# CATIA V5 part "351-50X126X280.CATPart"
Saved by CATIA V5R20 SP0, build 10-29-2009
Part number: 351-50X126X280
Definition: NONE
Nomenclature: 351-50X126X280
Source: Unknown
Description: 351-50X126X280
Bounding box of the stored display mesh (mm): x -10 to 270, y -32.5 to 32.5, z -32.5 to 32.5
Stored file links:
  C:\Users\Utente\Desktop\IO LAVORO\3D X SITO CF\X SITO\PLASTICA\351\351-50X126X280.CATPart
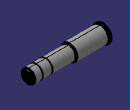
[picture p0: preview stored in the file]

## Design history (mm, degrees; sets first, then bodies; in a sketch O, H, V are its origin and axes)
Body1 "351-50X126X280" (main body)
  Solid1: solid without history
